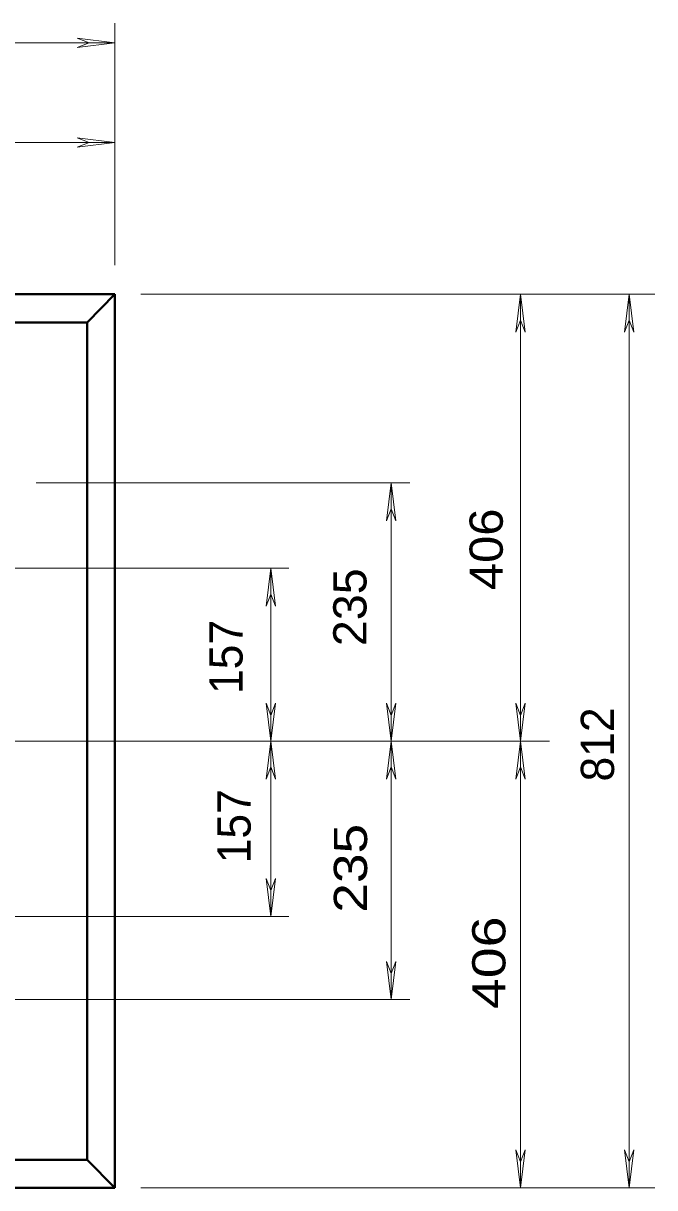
# Model space of a CAD drawing. Extents: x 312583 to 312854, y 144419 to 144597.
# Drawn here: x 312776.52 to 312790.95, y 144473.22 to 144499.87 of the extents above; entities that cross this region are included whole.
import ezdxf

# ---------------------------------------------------------------- set-up
doc = ezdxf.new("R2010")
doc.units = 0
doc.header["$LTSCALE"] = 0.3
doc.layers.add('1', color=7, linetype='Continuous', lineweight=25)
doc.layers.add('2', color=7, linetype='Continuous', lineweight=13)

msp = doc.modelspace()

# ---------------------------------------------------------------- linework, layer by layer
at = {"layer": '1', "lineweight": 40}
for p, q in [((312746.6716, 144493.6692), (312778.611, 144493.6692)), ((312777.9746, 144493.0252), (312778.611, 144493.6692)), ((312778.611, 144493.6692), (312778.611, 144473.2222)), ((312747.308, 144493.0252), (312777.9746, 144493.0252)), ((312777.9746, 144493.0252), (312777.9746, 144473.8585)), ((312747.308, 144473.8585), (312777.9746, 144473.8585)), ((312777.9746, 144473.8585), (312778.611, 144473.2222)), ((312746.6716, 144473.2222), (312778.611, 144473.2222))]:
    msp.add_line(p, q, dxfattribs=at)
at = {"layer": '2'}
for p, q in [((312778.611, 144494.3362), (312778.611, 144499.8715)), ((312777.7446, 144499.5342), (312778.0206, 144499.4268)), ((312778.611, 144499.4268), (312777.7446, 144499.5342)), ((312733.8913, 144499.4268), (312778.611, 144499.4268)), ((312777.7446, 144499.3195), (312778.0206, 144499.4268)), ((312778.611, 144499.4268), (312777.7446, 144499.3195)), ((312777.7446, 144497.2495), (312778.0206, 144497.1422)), ((312778.611, 144497.1422), (312777.7446, 144497.2495)), ((312777.7446, 144497.0348), (312778.0206, 144497.1422)), ((312778.611, 144497.1422), (312777.7446, 144497.0348)), ((312779.2013, 144493.6692), (312790.9543, 144493.6692)), ((312787.8876, 144493.6692), (312787.7803, 144492.8028)), ((312787.8876, 144493.6692), (312787.995, 144492.8028)), ((312790.3716, 144493.6692), (312790.2643, 144492.8028)), ((312790.3716, 144473.2222), (312790.3716, 144493.6692)), ((312790.3716, 144493.6692), (312790.479, 144492.8028)), ((312787.7803, 144492.8028), (312787.8876, 144493.0788)), ((312787.995, 144492.8028), (312787.8876, 144493.0788)), ((312790.2643, 144492.8028), (312790.3716, 144493.0788)), ((312790.479, 144492.8028), (312790.3716, 144493.0788)), ((312776.8093, 144489.3528), (312785.3576, 144489.3528)), ((312784.9283, 144489.3528), (312784.821, 144488.4865)), ((312784.9283, 144489.3528), (312785.0356, 144488.4865)), ((312784.821, 144488.4865), (312784.9283, 144488.7625)), ((312785.0356, 144488.4865), (312784.9283, 144488.7625)), ((312763.937, 144487.3978), (312782.59, 144487.3978)), ((312782.176, 144487.3978), (312782.0686, 144486.5315)), ((312782.176, 144483.4418), (312782.176, 144487.3978)), ((312782.176, 144487.3978), (312782.2833, 144486.5315)), ((312782.0686, 144486.5315), (312782.176, 144486.8075)), ((312782.2833, 144486.5315), (312782.176, 144486.8075)), ((312782.0686, 144484.3082), (312782.176, 144484.0322)), ((312782.176, 144483.4418), (312782.0686, 144484.3082)), ((312782.2833, 144484.3082), (312782.176, 144484.0322)), ((312782.176, 144483.4418), (312782.2833, 144484.3082)), ((312784.821, 144484.3082), (312784.9283, 144484.0322)), ((312784.9283, 144483.4418), (312784.821, 144484.3082)), ((312785.0356, 144484.3082), (312784.9283, 144484.0322)), ((312784.9283, 144483.4418), (312785.0356, 144484.3082)), ((312787.7803, 144484.3082), (312787.8876, 144484.0322)), ((312787.8876, 144483.4418), (312787.7803, 144484.3082)), ((312787.995, 144484.3082), (312787.8876, 144484.0322)), ((312787.8876, 144483.4418), (312787.995, 144484.3082)), ((312770.5993, 144483.4418), (312788.547, 144483.4418)), ((312782.176, 144483.4418), (312782.0686, 144482.5755)), ((312782.176, 144479.4322), (312782.176, 144483.4418)), ((312782.176, 144483.4418), (312782.2833, 144482.5755)), ((312784.9283, 144483.4418), (312784.821, 144482.5755)), ((312784.9283, 144483.4418), (312785.0356, 144482.5755)), ((312787.8876, 144483.4418), (312787.7803, 144482.5755)), ((312787.8876, 144483.4418), (312787.995, 144482.5755)), ((312782.0686, 144482.5755), (312782.176, 144482.8515)), ((312782.2833, 144482.5755), (312782.176, 144482.8515)), ((312784.821, 144482.5755), (312784.9283, 144482.8515)), ((312785.0356, 144482.5755), (312784.9283, 144482.8515)), ((312787.7803, 144482.5755), (312787.8876, 144482.8515)), ((312787.995, 144482.5755), (312787.8876, 144482.8515)), ((312782.0686, 144480.2985), (312782.176, 144480.0225)), ((312782.176, 144479.4322), (312782.0686, 144480.2985)), ((312782.2833, 144480.2985), (312782.176, 144480.0225)), ((312782.176, 144479.4322), (312782.2833, 144480.2985)), ((312771.182, 144479.4322), (312782.59, 144479.4322)), ((312784.821, 144478.3972), (312784.9283, 144478.1212)), ((312784.9283, 144477.5308), (312784.821, 144478.3972)), ((312785.0356, 144478.3972), (312784.9283, 144478.1212)), ((312784.9283, 144477.5308), (312785.0356, 144478.3972)), ((312774.9846, 144477.5308), (312785.3576, 144477.5308)), ((312787.7803, 144474.0885), (312787.8876, 144473.8125)), ((312787.8876, 144473.2222), (312787.7803, 144474.0885)), ((312787.995, 144474.0885), (312787.8876, 144473.8125)), ((312787.8876, 144473.2222), (312787.995, 144474.0885)), ((312790.2643, 144474.0885), (312790.3716, 144473.8125)), ((312790.3716, 144473.2222), (312790.2643, 144474.0885)), ((312790.479, 144474.0885), (312790.3716, 144473.8125)), ((312790.3716, 144473.2222), (312790.479, 144474.0885)), ((312779.2013, 144473.2222), (312790.9543, 144473.2222))]:
    msp.add_line(p, q, dxfattribs=at)
for points in [[(312762.6413, 144497.1422), (312770.5456, 144497.1422), (312778.611, 144497.1422)], [(312787.8876, 144473.2222), (312787.8876, 144483.4418), (312787.8876, 144493.6692)], [(312784.9283, 144477.5308), (312784.9283, 144483.4418), (312784.9283, 144489.3528)]]:
    msp.add_lwpolyline(points, dxfattribs=at)

# ---------------------------------------------------------------- texts
for s, width, p in [('406', 1.1, (312787.4805, 144486.9004)), ('235', 1.05, (312784.3636, 144485.6163)), ('235 ', 1.2, (312784.3777, 144479.5148)), ('406 ', 1.25, (312787.5411, 144477.3102))]:
    msp.add_text(s, height=0.76, rotation=90, dxfattribs=dict(at, width=width)).set_placement(p)
for s, p in [('157', (312781.5303, 144484.5215)), ('812', (312790.0251, 144482.5189)), ('157', (312781.7156, 144480.6459))]:
    msp.add_text(s, height=0.76, rotation=90, dxfattribs=at).set_placement(p)

doc.saveas('drawing.dxf')
